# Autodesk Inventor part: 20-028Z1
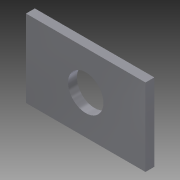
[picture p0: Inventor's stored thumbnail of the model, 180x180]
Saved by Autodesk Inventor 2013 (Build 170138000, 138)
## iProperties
Shininess: 64.0
Length Units: 11269
Angle Units: 11279
Time Units: 11290
Mass Units: 11286
Length Display Precision: 3
Angle Display Precision: 2
Compacted: True
Created: 2003-01
Part Number: 20-028Z1
Material: Stahl (hohe Festigk., niedr. Legier.)
Vendor: PARKER IPS
Document SubType Name: Modeling
Designer: Autodesk, Inc.
Description: FLAT PLATE FASTENER (w/o screw)
Catalog Web Link: http://www.parker.com/ead/cm1.asp?cmid=809
Mass: 6.62064 g
Surface Area: 10.7273 cm^2
Volume: 0.844469 cm^3
Density: 7.84 g/cm^3
Density: 0.0
Volumn: 0.0
Area: 0.0
PropertySet Name: Model Information
Control State: 0
Master: False
Checked Out: False
CAGE: 08JJ3
NEXT HIGHER ASSY 01: ---
Author: Autodesk, Inc.
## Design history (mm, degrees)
sketch "Sketch1"
  geometry: L1 (-13.5, -8.75)-(13.5, -8.75); L2 (13.5, -8.75)-(13.5, 8.75); L3 (13.5, 8.75)-(-13.5, 8.75); L4 (-13.5, 8.75)-(-13.5, -8.75); L5 (0, 0)-(0, 8.75); L6 (0, 0)-(13.5, 0); C1 r 4 at (0, 0)
  constraints: 12 end point, 3 perpendicular, 2 midpoint, 2 parallel, 1 centre point, 1 coincident, 1 horizontal, 1 other
  dimensions: "d0" = 27 distance of L1.start L1.end; "d2" = 8 diameter of C1; "d3" = 17.5 distance of L1.end L2.end
extrude "Extrusion1" new body sketch "Sketch1" stored distance "d4" = 2; taper "d5" = 0 deg
body "Solid1"
